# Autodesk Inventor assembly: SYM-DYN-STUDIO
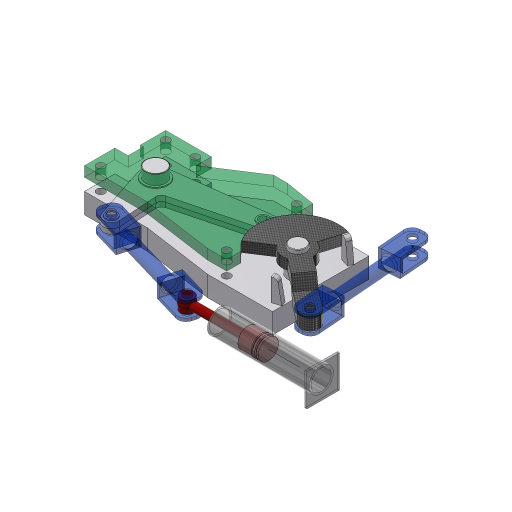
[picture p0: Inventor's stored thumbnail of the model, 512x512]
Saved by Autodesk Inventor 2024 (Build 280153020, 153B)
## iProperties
Company: ATC
Shininess: 64.0
Angle Display Precision: 2
Document Length Units: 11269
Document Angle Units: 11279
Document Time Units: 11290
Document Mass Units: 11283
Document Length Units Precision: 3
Document Angle Units Precision: 2
Created: 2023-03
Part Number: SYM-DYN-STUDIO
Document SubType Name: Zespół
Designer: Andrzej Jaskulski
Stock Number: SYM-DYN-STUDIO
Checked By: A.J.
Engr Approved By: Andrzej Jaskulski
Mfg Approved By: Andrzej Jaskulski
Authority: A.J.
Density: 0.0
Volumn: 0.0
Area: 0.0
PropertySet Name: Model Information
Control State: 0
Master: False
Checked Out: False
Title: A.J.: Kurs R2024-MEP
Author: Andrzej Jaskulski
Revision Number: 1/24
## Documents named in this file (9)
- C:\Users\AndJas\Documents\R2024-MEP\Obszar roboczy\SPEC-STUDIO\SYM-DYN-STUDIO.iam
- C:\Users\AndJas\Documents\R2024-MEP\Obszar roboczy\SPEC-STUDIO\Płyta górna.ipt
- C:\Users\AndJas\Documents\R2024-MEP\Obszar roboczy\SPEC-STUDIO\Dźwignia kątowa.ipt
- C:\Users\AndJas\Documents\R2024-MEP\Obszar roboczy\SPEC-STUDIO\Kołek.ipt
- C:\Users\AndJas\Documents\R2024-MEP\Obszar roboczy\SPEC-STUDIO\Płyta dolna.ipt
- C:\Users\AndJas\Documents\R2024-MEP\Obszar roboczy\SPEC-STUDIO\Wahacz.ipt
- C:\Users\AndJas\Documents\R2024-MEP\Obszar roboczy\SPEC-STUDIO\Łącznik.ipt
- C:\Users\AndJas\Documents\R2024-MEP\Obszar roboczy\SPEC-STUDIO\Suwak.ipt
- C:\Users\AndJas\Documents\R2024-MEP\Obszar roboczy\SPEC-STUDIO\Korpus.ipt
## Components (13 placed, 8 different names)
1. Płyta dolna:1 — Zestawiające:1, Zestawiające:2, Zestawiające:3, Napędowe, Zestawiające:4, Zestawiające:5, Suwak2, Zestawiający:13, Zestawiający:14, Kąt:2, Równoległy:1, Zestawiający:15
2. Płyta górna:1 — Wstawiające:6, Zestawiające:4, Wstaw:9, Wstaw:10, Wstaw:11, Wstaw:12
3. Kołek:1 — Wstaw:9
4. Kołek:2 — Wstawiające:6
5. Kołek:3 — Wstaw:10
6. Kołek:4 — Wstaw:11
7. Kołek:5 — Wstaw:12
8. Dźwignia kątowa:1 — Zestawiające:3, Przejściowy:1, Zestawiające:5, Wstaw:13
9. Łącznik:1 — Suwak2, Walec2
10. Wahacz:1 — Zestawiające:1, Zestawiające:2, Przejściowy:1, Napędowe, Walec2
11. Łącznik:2 — Wstaw:13, Zestawiający:16
12. Suwak:1 — Zestawiający:13, Zestawiający:15, Zestawiający:16
13. Korpus:1 — Zestawiający:14, Kąt:2, Równoległy:1
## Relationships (21: Mate 11, Insert 6, Angle 2, Transitional 1, Flush 1)
- Zestawiające:1 [Mate]: Płyta dolna:1 ↔ Wahacz:1
- Zestawiające:2 [Mate]: Płyta dolna:1 ↔ Wahacz:1
- Zestawiające:3 [Mate]: Płyta dolna:1 ↔ Dźwignia kątowa:1
- Przejściowy:1 [Transitional]: Dźwignia kątowa:1 ↔ Wahacz:1
- Napędowe [Angle]: Płyta dolna:1 ↔ Wahacz:1
- Wstawiające:6 [Insert]: Płyta górna:1 ↔ Kołek:2
- Zestawiające:4 [Mate]: Płyta dolna:1 ↔ Płyta górna:1
- Zestawiające:5 [Mate]: Płyta dolna:1 ↔ Dźwignia kątowa:1
- Suwak2 [Mate]: Płyta dolna:1 ↔ Łącznik:1
- Walec2 [Mate]: Łącznik:1 ↔ Wahacz:1
- Wstaw:9 [Insert]: Płyta górna:1 ↔ Kołek:1
- Wstaw:10 [Insert]: Płyta górna:1 ↔ Kołek:3
- Wstaw:11 [Insert]: Płyta górna:1 ↔ Kołek:4
- Wstaw:12 [Insert]: Płyta górna:1 ↔ Kołek:5
- Zestawiający:13 [Mate]: Płyta dolna:1 ↔ Suwak:1
- Zestawiający:14 [Mate]: Płyta dolna:1 ↔ Korpus:1
- Kąt:2 [Angle]: Płyta dolna:1 ↔ Korpus:1
- Równoległy:1 [Flush]: Płyta dolna:1 ↔ Korpus:1
- Wstaw:13 [Insert]: Dźwignia kątowa:1 ↔ Łącznik:2
- Zestawiający:15 [Mate]: Płyta dolna:1 ↔ Suwak:1
- Zestawiający:16 [Mate]: Łącznik:2 ↔ Suwak:1
## Named parameters: Simulation_Timeline = 0
